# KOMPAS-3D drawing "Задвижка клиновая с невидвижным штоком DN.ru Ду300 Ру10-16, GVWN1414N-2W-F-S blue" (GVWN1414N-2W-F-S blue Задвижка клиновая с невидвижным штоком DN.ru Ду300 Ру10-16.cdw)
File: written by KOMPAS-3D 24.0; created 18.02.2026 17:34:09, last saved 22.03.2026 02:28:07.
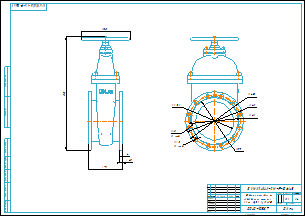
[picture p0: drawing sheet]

Document properties: Автор: R2D2; Форматы листов документа: A2; Полное имя файла: GVWN1414N-2W-F-S blue Задвижка клиновая с невидвижным штоком DN.ru Ду300 Ру10-16.m3d; Масса: 100; Наименование: Задвижка клиновая с невидвижным штоком DN.ru Ду300 Ру10-16; Количество листов документа: 1; Примечание: D040-10587

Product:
- Part/product: Задвижка клиновая с невидвижным штоком DN.ru Ду300 Ру10-16  | designation GVWN1414N-2W-F-S blue
    Масса: 100
    Раздел спецификации: Прочие изделия
    Примечание: D040-10587

Views: Вид 1, Спереди, Проекционный вид 2
Referenced files in E:\Работа\Зайцев\GVWN1414N-2W-F-S blue Задвижка клиновая с невидвижным штоком DN.ru Ду40-300 Ру10-16\DN300\: GVWN1414N-2W-F-S blue Задвижка клиновая с невидвижным штоком DN.ru Ду300 Ру10-16.m3d
Referenced files in E:\Работа\Зайцев\Для компаса\: чертеж DN.ru А3.cdt
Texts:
  GVWN1414N-2W-F-S blue
  чертеж DN.ru А3.cdt
  Задвижка клиновая с
  невидвижным штоком
  DN.ru Ду300 Ру10-16
  Задвижка клиновая с невидвижным штоком DN.ru Ду300 Ру10-16
  GVWN1414N-2W-F-S blue Задвижка клиновая с невидвижным штоком DN.ru Ду300 Ру10-16
Dimensions and other numbers on the sheet: 0; 3; 2; 4; 270; 24,5; 890; 380; 460; 410; 400; 370; 300; 28; 12 отв.; 23; 1:4; 1; 100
